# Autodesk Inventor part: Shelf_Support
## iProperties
Shininess: 64.0
Length Units: 11272
Angle Units: 11279
Time Units: 11290
Mass Units: 11286
Length Display Precision: 3
Angle Display Precision: 2
Compacted: True
Part Number: Shelf_Support
Document SubType Name: Modeling
Created: 2005-01
Designer: John Blackburn
Material: Aluminum-6061
Manufacturer: Standard
Standards Organization: Custom
Density: 0.0
Volumn: 0.0
Area: 0.0
PropertySet Name: Model Information
Control State: 0
Master: False
Checked Out: False
Author: John Blackburn
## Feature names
1. Extrusion1
